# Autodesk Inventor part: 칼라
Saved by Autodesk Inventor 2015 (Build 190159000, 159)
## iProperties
Created: 2026-07
Part Number: 칼라
Material: 일반
Document SubType Name: Modeling
Designer: user
Density: 1 g/cm^3
Appearance: 기본값
Author: user
Author: jhkim
Creation Date: 2026-07-01
Sending System: Autodesk Inventor 2027
Preprocessor: ST-DEVELOPER v20.1
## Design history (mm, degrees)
node "칼라1"
node "솔리드1"
node "기준1"
